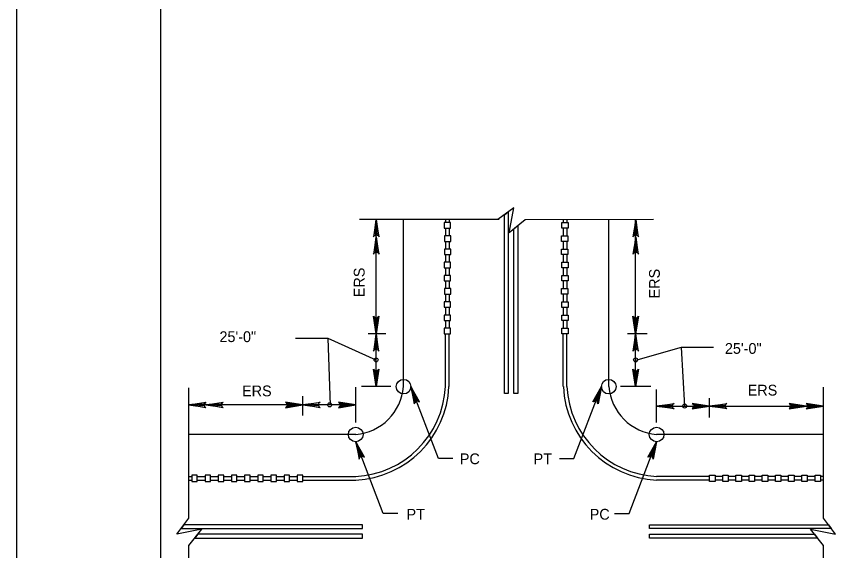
# Model space of a CAD drawing. Extents: x 632008 to 634206, y 294231 to 297795.
# Drawn here: x 632007.9 to 632240.2, y 296179.8 to 296328.3 of the extents above; entities that cross this region are included whole.
import ezdxf

# ---------------------------------------------------------------- set-up
doc = ezdxf.new("R2010")
doc.units = 0
for name, color, linetype in [('1', 7, 'Continuous'), ('Level 2', 7, 'Continuous'), ('PLT-BNDY', 7, 'Continuous')]:
    doc.layers.add(name, color=color, linetype=linetype)

msp = doc.modelspace()

# ---------------------------------------------------------------- linework, layer by layer
at = {"layer": '1'}
msp.add_lwpolyline([(632833.86, 296027.62), (632833.86, 296591.62), (632047.86, 296591.62), (632047.86, 296027.62), (632833.86, 296027.62), (632833.86, 296053.98), (632633.86, 296053.98), (632633.86, 296118.66), (632833.86, 296118.66), (632833.86, 296147.62), (632633.86, 296147.62), (632633.86, 296027.62), (632712.66, 296027.62), (632712.66, 296053.98), (632712.66, 296027.62), (632789.66, 296027.62), (632789.66, 296053.98), (632789.66, 296041.66), (632833.86, 296041.66)], dxfattribs=at)
for points in [[(632144.74, 296273.95), (632144.74, 296223.39), (632143.69, 296223.39), (632143.69, 296273.16)], [(632147.38, 296270.12), (632147.38, 296223.39), (632146.32, 296223.39), (632146.32, 296269.26)], [(632053.61, 296185.86), (632104.17, 296185.86), (632104.17, 296186.91), (632054.39, 296186.91)], [(632234.66, 296185.86), (632184.09, 296185.86), (632184.09, 296186.91), (632233.87, 296186.91)], [(632057.44, 296183.22), (632104.17, 296183.22), (632104.17, 296184.27), (632058.3, 296184.27)], [(632230.82, 296183.22), (632184.09, 296183.22), (632184.09, 296184.27), (632229.96, 296184.27)]]:
    msp.add_lwpolyline(points, close=True, dxfattribs=at)
at = {"layer": 'Level 2'}
for p, q in [((632146.28, 296275.11), (632141.85, 296271.79)), ((632144.94, 296268.14), (632146.28, 296275.11)), ((632142.16, 296271.79), (632103.33, 296271.79)), ((632107.93, 296225.33), (632107.97, 296271.86)), ((632115.57, 296225.33), (632115.57, 296271.79)), ((632127.22, 296271.79), (632127.22, 296270.96)), ((632128.23, 296271.79), (632128.23, 296270.96)), ((632149.44, 296271.78), (632144.94, 296268.14)), ((632185.15, 296271.79), (632149.44, 296271.78)), ((632160.05, 296271.78), (632160.05, 296270.96)), ((632161.06, 296271.78), (632161.06, 296270.96)), ((632172.71, 296225.33), (632172.71, 296271.79)), ((632180.19, 296225.33), (632180.19, 296271.79)), ((632127.22, 296269.43), (632127.22, 296267.29)), ((632128.23, 296269.43), (632128.23, 296267.29)), ((632160.05, 296269.43), (632160.05, 296267.29)), ((632161.06, 296269.43), (632161.06, 296267.29)), ((632127.22, 296265.76), (632127.22, 296263.62)), ((632128.23, 296265.76), (632128.23, 296263.62)), ((632160.05, 296265.76), (632160.05, 296263.61)), ((632161.06, 296265.76), (632161.06, 296263.61)), ((632127.22, 296262.09), (632127.22, 296259.94)), ((632128.23, 296262.09), (632128.23, 296259.94)), ((632160.05, 296262.08), (632160.05, 296259.94)), ((632161.06, 296262.08), (632161.06, 296259.94)), ((632127.22, 296258.41), (632127.22, 296256.27)), ((632128.23, 296258.41), (632128.23, 296256.27)), ((632160.05, 296258.41), (632160.05, 296256.27)), ((632161.06, 296258.41), (632161.06, 296256.27)), ((632127.22, 296254.74), (632127.22, 296252.6)), ((632128.23, 296254.74), (632128.23, 296252.6)), ((632160.05, 296254.74), (632160.05, 296252.6)), ((632161.06, 296254.74), (632161.06, 296252.6)), ((632127.22, 296251.07), (632127.22, 296248.93)), ((632128.23, 296251.07), (632128.23, 296248.93)), ((632160.05, 296251.07), (632160.05, 296248.92)), ((632161.06, 296251.07), (632161.06, 296248.92)), ((632127.22, 296247.4), (632127.22, 296245.25)), ((632128.23, 296247.4), (632128.23, 296245.25)), ((632160.05, 296247.39), (632160.05, 296245.25)), ((632161.06, 296247.39), (632161.06, 296245.25)), ((632127.22, 296243.72), (632127.22, 296241.58)), ((632128.23, 296243.72), (632128.23, 296241.58)), ((632160.05, 296243.72), (632160.05, 296241.58)), ((632161.06, 296243.72), (632161.06, 296241.58)), ((632094.48, 296238.78), (632107.89, 296232.76)), ((632110.67, 296240.06), (632105.72, 296240.06)), ((632127.22, 296225.34), (632127.22, 296240.05)), ((632128.23, 296225.34), (632128.23, 296240.05)), ((632160.05, 296225.33), (632160.05, 296240.05)), ((632161.06, 296225.33), (632161.06, 296240.05)), ((632183.37, 296240.06), (632177.93, 296240.06)), ((632192.82, 296236.25), (632180.14, 296232.64)), ((632055.77, 296188.74), (632055.77, 296225.04)), ((632102.25, 296215.34), (632102.25, 296225.17)), ((632112.03, 296225.33), (632103.82, 296225.33)), ((632184.45, 296225.33), (632175.93, 296225.33)), ((632186.03, 296215.34), (632186.03, 296224.5)), ((632232.49, 296188.74), (632232.49, 296225.17)), ((632087.53, 296217.3), (632087.53, 296222.69)), ((632200.75, 296216.75), (632200.75, 296222.13)), ((632102.26, 296220.25), (632055.7, 296220.24)), ((632186.03, 296219.92), (632232.49, 296219.92)), ((632102.25, 296212.02), (632055.77, 296212.02)), ((632232.49, 296212.02), (632186.03, 296212.02)), ((632055.79, 296200.33), (632056.61, 296200.33)), ((632055.79, 296199.32), (632056.61, 296199.32)), ((632058.14, 296200.33), (632060.29, 296200.33)), ((632058.14, 296199.32), (632060.29, 296199.32)), ((632061.82, 296200.33), (632063.96, 296200.33)), ((632061.82, 296199.32), (632063.96, 296199.32)), ((632065.49, 296200.33), (632067.63, 296200.33)), ((632065.49, 296199.32), (632067.63, 296199.32)), ((632069.16, 296200.33), (632071.3, 296200.33)), ((632069.16, 296199.32), (632071.3, 296199.32)), ((632072.83, 296200.33), (632074.98, 296200.33)), ((632072.83, 296199.32), (632074.98, 296199.32)), ((632076.51, 296200.33), (632078.65, 296200.33)), ((632076.51, 296199.32), (632078.65, 296199.32)), ((632080.18, 296200.33), (632082.32, 296200.33)), ((632080.18, 296199.32), (632082.32, 296199.32)), ((632083.85, 296200.33), (632085.99, 296200.33)), ((632083.85, 296199.32), (632085.99, 296199.32)), ((632087.52, 296200.33), (632102.25, 296200.33)), ((632087.52, 296199.32), (632102.25, 296199.32)), ((632200.76, 296200.33), (632186.03, 296200.33)), ((632200.76, 296199.32), (632186.03, 296199.32)), ((632204.43, 296200.33), (632202.29, 296200.33)), ((632204.43, 296199.32), (632202.29, 296199.32)), ((632208.1, 296200.33), (632205.96, 296200.33)), ((632208.1, 296199.32), (632205.96, 296199.32)), ((632211.77, 296200.33), (632209.63, 296200.33)), ((632211.77, 296199.32), (632209.63, 296199.32)), ((632215.45, 296200.33), (632213.3, 296200.33)), ((632215.45, 296199.32), (632213.3, 296199.32)), ((632219.12, 296200.33), (632216.98, 296200.33)), ((632219.12, 296199.32), (632216.98, 296199.32)), ((632222.79, 296200.33), (632220.65, 296200.33)), ((632222.79, 296199.32), (632220.65, 296199.32)), ((632226.46, 296200.33), (632224.32, 296200.33)), ((632226.46, 296199.32), (632224.32, 296199.32)), ((632230.14, 296200.33), (632227.99, 296200.33)), ((632230.14, 296199.32), (632227.99, 296199.32)), ((632232.49, 296200.33), (632231.67, 296200.33)), ((632232.49, 296199.32), (632231.67, 296199.32)), ((632052.45, 296184.31), (632055.77, 296188.74)), ((632235.81, 296184.31), (632232.49, 296188.74)), ((632059.42, 296185.66), (632052.45, 296184.31)), ((632055.77, 296181.16), (632059.42, 296185.66)), ((632232.49, 296181.16), (632228.84, 296185.66)), ((632228.84, 296185.66), (632235.81, 296184.31)), ((632055.77, 296141.49), (632055.77, 296181.16)), ((632232.49, 296141.49), (632232.49, 296181.16))]:
    msp.add_line(p, q, dxfattribs=at)
for points in [[(632108.55, 296267.26), (632108.22, 296267.42), (632107.97, 296271.86), (632108.55, 296267.26), (632108.75, 296267.02), (632107.97, 296271.86), (632107.75, 296267.43), (632107.43, 296267.27), (632107.97, 296271.86), (632107.2, 296267.02), (632107.43, 296267.27)], [(632180.8, 296267.26), (632180.47, 296267.42), (632180.22, 296271.86), (632180.8, 296267.26), (632181, 296267.02), (632180.22, 296271.86), (632180, 296267.43), (632179.68, 296267.27), (632180.22, 296271.86), (632179.45, 296267.02), (632179.68, 296267.27)], [(632108.55, 296262.44), (632108.22, 296262.61), (632107.97, 296267.04), (632108.55, 296262.44), (632108.75, 296262.2), (632107.97, 296267.04), (632107.75, 296262.61), (632107.43, 296262.45), (632107.97, 296267.04), (632107.2, 296262.2), (632107.43, 296262.45)], [(632180.8, 296262.44), (632180.47, 296262.61), (632180.22, 296267.04), (632180.8, 296262.44), (632181, 296262.2), (632180.22, 296267.04), (632180, 296262.61), (632179.68, 296262.45), (632180.22, 296267.04), (632179.45, 296262.2), (632179.68, 296262.45)], [(632108.52, 296244.66), (632108.19, 296244.49), (632107.94, 296240.06), (632108.52, 296244.66), (632108.72, 296244.9), (632107.94, 296240.06), (632107.72, 296244.49), (632107.4, 296244.65), (632107.94, 296240.06), (632107.17, 296244.9), (632107.4, 296244.65)], [(632180.77, 296244.66), (632180.44, 296244.49), (632180.19, 296240.06), (632180.77, 296244.66), (632180.97, 296244.9), (632180.19, 296240.06), (632179.97, 296244.49), (632179.65, 296244.65), (632180.19, 296240.06), (632179.42, 296244.9), (632179.65, 296244.65)], [(632085.44, 296238.78), (632094.48, 296238.78), (632095.11, 296220.19)], [(632108.5, 296235.46), (632108.17, 296235.62), (632107.93, 296240.06), (632108.5, 296235.46), (632108.71, 296235.22), (632107.93, 296240.06), (632107.71, 296235.63), (632107.38, 296235.47), (632107.93, 296240.06), (632107.16, 296235.22), (632107.38, 296235.47)], [(632180.77, 296235.46), (632180.44, 296235.62), (632180.19, 296240.06), (632180.77, 296235.46), (632180.97, 296235.22), (632180.19, 296240.06), (632179.97, 296235.63), (632179.65, 296235.47), (632180.19, 296240.06), (632179.42, 296235.22), (632179.65, 296235.47)], [(632201.86, 296236.25), (632192.82, 296236.25), (632193.76, 296219.89)], [(632108.5, 296229.94), (632108.17, 296229.77), (632107.93, 296225.33), (632108.5, 296229.94), (632108.71, 296230.17), (632107.93, 296225.33), (632107.71, 296229.76), (632107.38, 296229.92), (632107.93, 296225.33), (632107.16, 296230.17), (632107.38, 296229.92)], [(632180.77, 296229.94), (632180.44, 296229.77), (632180.19, 296225.33), (632180.77, 296229.94), (632180.97, 296230.17), (632180.19, 296225.33), (632179.97, 296229.76), (632179.65, 296229.92), (632180.19, 296225.33), (632179.42, 296230.17), (632179.65, 296229.92)], [(632129.32, 296205.36), (632125.27, 296205.36), (632117.59, 296225.33)], [(632119.74, 296221.22), (632119.37, 296221.26), (632117.59, 296225.33), (632119.74, 296221.22), (632120.01, 296221.07), (632117.59, 296225.33), (632118.93, 296221.11), (632118.68, 296220.84), (632117.59, 296225.33), (632118.56, 296220.53), (632118.68, 296220.84)], [(632158.96, 296205.36), (632163.01, 296205.36), (632170.69, 296225.33)], [(632168.54, 296221.22), (632168.91, 296221.26), (632170.69, 296225.33), (632168.54, 296221.22), (632168.27, 296221.07), (632170.69, 296225.33), (632169.35, 296221.11), (632169.6, 296220.84), (632170.69, 296225.33), (632169.72, 296220.53), (632169.6, 296220.84)], [(632060.3, 296219.66), (632060.14, 296219.99), (632055.7, 296220.24), (632060.3, 296219.66), (632060.54, 296219.46), (632055.7, 296220.24), (632060.13, 296220.45), (632060.29, 296220.78), (632055.7, 296220.24), (632060.54, 296221), (632060.29, 296220.78)], [(632065.12, 296219.66), (632064.96, 296219.99), (632060.52, 296220.24), (632065.12, 296219.66), (632065.36, 296219.46), (632060.52, 296220.24), (632064.95, 296220.45), (632065.11, 296220.78), (632060.52, 296220.24), (632065.36, 296221), (632065.11, 296220.78)], [(632082.93, 296219.67), (632083.1, 296220.01), (632087.53, 296220.25), (632082.93, 296219.67), (632082.69, 296219.47), (632087.53, 296220.25), (632083.1, 296220.47), (632082.94, 296220.8), (632087.53, 296220.25), (632082.69, 296221.02), (632082.94, 296220.8)], [(632092.13, 296219.67), (632091.96, 296220.01), (632087.53, 296220.25), (632092.13, 296219.67), (632092.37, 296219.47), (632087.53, 296220.25), (632091.96, 296220.47), (632092.12, 296220.8), (632087.53, 296220.25), (632092.37, 296221.02), (632092.12, 296220.8)], [(632097.65, 296219.67), (632097.82, 296220.01), (632102.26, 296220.25), (632097.65, 296219.67), (632097.42, 296219.47), (632102.26, 296220.25), (632097.83, 296220.47), (632097.67, 296220.8), (632102.26, 296220.25), (632097.42, 296221.02), (632097.67, 296220.8)], [(632190.63, 296219.34), (632190.46, 296219.67), (632186.03, 296219.92), (632190.63, 296219.34), (632190.87, 296219.14), (632186.03, 296219.92), (632190.46, 296220.14), (632190.62, 296220.47), (632186.03, 296219.92), (632190.87, 296220.69), (632190.62, 296220.47)], [(632196.15, 296219.34), (632196.32, 296219.67), (632200.75, 296219.92), (632196.15, 296219.34), (632195.91, 296219.14), (632200.75, 296219.92), (632196.33, 296220.14), (632196.16, 296220.47), (632200.75, 296219.92), (632195.91, 296220.69), (632196.16, 296220.47)], [(632205.36, 296219.34), (632205.19, 296219.67), (632200.75, 296219.92), (632205.36, 296219.34), (632205.59, 296219.14), (632200.75, 296219.92), (632205.18, 296220.14), (632205.34, 296220.47), (632200.75, 296219.92), (632205.59, 296220.69), (632205.34, 296220.47)], [(632223.14, 296219.34), (632223.31, 296219.67), (632227.74, 296219.91), (632223.14, 296219.34), (632222.9, 296219.14), (632227.74, 296219.91), (632223.31, 296220.13), (632223.15, 296220.46), (632227.74, 296219.91), (632222.9, 296220.68), (632223.15, 296220.46)], [(632227.9, 296219.34), (632228.07, 296219.67), (632232.51, 296219.91), (632227.9, 296219.34), (632227.67, 296219.14), (632232.51, 296219.91), (632228.08, 296220.13), (632227.92, 296220.46), (632232.51, 296219.91), (632227.67, 296220.68), (632227.92, 296220.46)], [(632104.4, 296205.88), (632104.03, 296205.92), (632102.25, 296209.99), (632104.4, 296205.88), (632104.67, 296205.73), (632102.25, 296209.99), (632103.59, 296205.77), (632103.34, 296205.5), (632102.25, 296209.99), (632103.22, 296205.19), (632103.34, 296205.5)], [(632113.98, 296190.02), (632109.92, 296190.02), (632102.25, 296209.99)], [(632174.3, 296190.02), (632178.35, 296190.02), (632186.03, 296209.99)], [(632183.88, 296205.88), (632184.25, 296205.92), (632186.03, 296209.99), (632183.88, 296205.88), (632183.61, 296205.73), (632186.03, 296209.99), (632184.69, 296205.77), (632184.94, 296205.5), (632186.03, 296209.99), (632185.06, 296205.19), (632184.94, 296205.5)]]:
    msp.add_lwpolyline(points, dxfattribs=at)
for points in [[(632128.68, 296269.43), (632128.68, 296270.96), (632126.84, 296270.96), (632126.84, 296269.43)], [(632159.6, 296269.43), (632159.6, 296270.96), (632161.44, 296270.96), (632161.44, 296269.43)], [(632128.77, 296265.76), (632128.77, 296267.29), (632126.93, 296267.29), (632126.93, 296265.76)], [(632159.51, 296265.76), (632159.51, 296267.29), (632161.35, 296267.29), (632161.35, 296265.76)], [(632128.77, 296262.09), (632128.77, 296263.62), (632126.93, 296263.62), (632126.93, 296262.09)], [(632159.51, 296262.08), (632159.51, 296263.61), (632161.35, 296263.61), (632161.35, 296262.08)], [(632128.68, 296258.41), (632128.68, 296259.94), (632126.84, 296259.94), (632126.84, 296258.41)], [(632159.6, 296258.41), (632159.6, 296259.94), (632161.44, 296259.94), (632161.44, 296258.41)], [(632128.68, 296254.74), (632128.68, 296256.27), (632126.84, 296256.27), (632126.84, 296254.74)], [(632159.6, 296254.74), (632159.6, 296256.27), (632161.44, 296256.27), (632161.44, 296254.74)], [(632128.77, 296251.07), (632128.77, 296252.6), (632126.93, 296252.6), (632126.93, 296251.07)], [(632159.51, 296251.07), (632159.51, 296252.6), (632161.35, 296252.6), (632161.35, 296251.07)], [(632128.68, 296247.4), (632128.68, 296248.93), (632126.84, 296248.93), (632126.84, 296247.4)], [(632159.6, 296247.39), (632159.6, 296248.92), (632161.44, 296248.92), (632161.44, 296247.39)], [(632128.68, 296243.72), (632128.68, 296245.25), (632126.84, 296245.25), (632126.84, 296243.72)], [(632159.6, 296243.72), (632159.6, 296245.25), (632161.44, 296245.25), (632161.44, 296243.72)], [(632128.68, 296240.05), (632128.68, 296241.58), (632126.84, 296241.58), (632126.84, 296240.05)], [(632159.6, 296240.05), (632159.6, 296241.58), (632161.44, 296241.58), (632161.44, 296240.05)], [(632058.14, 296200.74), (632056.61, 296200.74), (632056.61, 296198.91), (632058.14, 296198.91)], [(632061.82, 296200.74), (632060.29, 296200.74), (632060.29, 296198.91), (632061.82, 296198.91)], [(632065.49, 296200.74), (632063.96, 296200.74), (632063.96, 296198.91), (632065.49, 296198.91)], [(632069.16, 296200.74), (632067.63, 296200.74), (632067.63, 296198.91), (632069.16, 296198.91)], [(632072.83, 296200.74), (632071.3, 296200.74), (632071.3, 296198.91), (632072.83, 296198.91)], [(632076.51, 296200.74), (632074.98, 296200.74), (632074.98, 296198.91), (632076.51, 296198.91)], [(632080.18, 296200.74), (632078.65, 296200.74), (632078.65, 296198.91), (632080.18, 296198.91)], [(632083.85, 296200.74), (632082.32, 296200.74), (632082.32, 296198.91), (632083.85, 296198.91)], [(632087.52, 296200.74), (632085.99, 296200.74), (632085.99, 296198.91), (632087.52, 296198.91)], [(632200.76, 296200.74), (632202.29, 296200.74), (632202.29, 296198.9), (632200.76, 296198.9)], [(632204.43, 296200.74), (632205.96, 296200.74), (632205.96, 296198.9), (632204.43, 296198.9)], [(632208.1, 296200.74), (632209.63, 296200.74), (632209.63, 296198.9), (632208.1, 296198.9)], [(632211.77, 296200.74), (632213.3, 296200.74), (632213.3, 296198.9), (632211.77, 296198.9)], [(632215.45, 296200.74), (632216.98, 296200.74), (632216.98, 296198.9), (632215.45, 296198.9)], [(632219.12, 296200.74), (632220.65, 296200.74), (632220.65, 296198.9), (632219.12, 296198.9)], [(632222.79, 296200.74), (632224.32, 296200.74), (632224.32, 296198.9), (632222.79, 296198.9)], [(632226.46, 296200.74), (632227.99, 296200.74), (632227.99, 296198.9), (632226.46, 296198.9)], [(632230.14, 296200.74), (632231.67, 296200.74), (632231.67, 296198.9), (632230.14, 296198.9)]]:
    msp.add_lwpolyline(points, close=True, dxfattribs=at)
for centre, radius in [((632107.94, 296232.78), 0.558), ((632180.19, 296232.78), 0.558), ((632115.57, 296225.33), 2.03), ((632172.71, 296225.33), 2.03), ((632094.98, 296220.27), 0.558), ((632193.83, 296219.92), 0.558), ((632102.25, 296212.02), 2.03), ((632186.03, 296212.02), 2.03)]:
    msp.add_circle(centre, radius, dxfattribs=at)
for centre, radius, start, end in [((632100.95, 296226.59), 26.29, 272.7214, 357.3646), ((632100.95, 296226.59), 27.3, 272.7214, 357.3646), ((632101.02, 296226.57), 14.6, 274.837, 355.163), ((632187.33, 296226.59), 27.3, 182.6354, 267.2786), ((632187.33, 296226.59), 26.29, 182.6354, 267.2786), ((632187.26, 296226.57), 14.6, 184.837, 265.163)]:
    msp.add_arc(centre, radius, start, end, dxfattribs=at)
at = {"layer": 'PLT-BNDY'}
msp.add_lwpolyline([(632007.86, 296606.62), (632848.86, 296606.62), (632848.86, 296012.62), (632007.86, 296012.62)], close=True, dxfattribs=at)

# ---------------------------------------------------------------- texts
at = {"layer": 'Level 2'}
for p in [(632104.72, 296250.2), (632186.92, 296249.87)]:
    msp.add_text('ERS', height=3, rotation=90, dxfattribs=at).set_placement(p)
for s, p in [('25\'-0"', (632064.31, 296237.73)), ('25\'-0"', (632205.04, 296234.46)), ('ERS', (632070.6, 296222.65)), ('ERS', (632211.38, 296222.86)), ('PC', (632131.24, 296203.75)), ('PT', (632151.78, 296203.75)), ('PT', (632116.39, 296188.33)), ('PC', (632167.4, 296188.33))]:
    msp.add_text(s, height=3, dxfattribs=at).set_placement(p)

doc.saveas('drawing.dxf')
